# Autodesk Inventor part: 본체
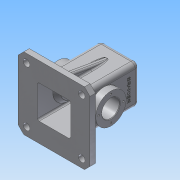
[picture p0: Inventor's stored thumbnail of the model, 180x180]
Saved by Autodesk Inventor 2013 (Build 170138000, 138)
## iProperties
Created: 2016-02
Part Number: 본체
Material: 알루미늄 6061
Document SubType Name: Modeling
Designer: Administrator
Density: 2.71 g/cm^3
Mass: 931.555 g
Surface Area: 1047.27 cm^2
Volume: 343.747 cm^3
Author: Administrator
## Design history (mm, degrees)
sketch "스케치3"
  geometry: L1 (-35, 35)-(35, 35); L2 (35, 35)-(35, -35); L3 (35, -35)-(-35, -35); L4 (-35, -35)-(-35, 35); L5 (-35, 35)-(35, -35); L6 (35, 35)-(-35, -35); 1 further point
  constraints: 12 end point, 2 midpoint, 2 parallel, 1 horizontal, 1 perpendicular
  dimensions: "d4" = 70 distance of L2.end L3.end; "d5" = 70 distance of L1.end L2.end
extrude "돌출2" new body sketch "스케치3" distance "d6" = 120; taper "d7" = 0 deg
feature "쉘2" dims "d8" = 5
sketch "스케치4"
  geometry: L1 (35, 35)-(-35, 35) reference; L2 (-35, 35)-(-35, -35) reference; L3 (-35, -35)-(35, -35) reference; L4 (35, -35)-(35, 35) reference; L5 (65, -65)-(-65, -65); L6 (-65, -65)-(-65, 65); L7 (-65, 65)-(65, 65); L8 (65, 65)-(65, -65); L9 (65, -65)-(-65, 65); L10 (-65, -65)-(65, 65); 1 further point
  constraints: 12 end point, 2 midpoint, 2 parallel, 1 horizontal, 1 perpendicular
  dimensions: "d9" = 130 distance of L6.end L7.end; "d10" = 130 distance of L5.end L6.end
extrude "돌출3" join sketch "스케치4" distance "d11" = 10; taper "d12" = 0 deg
sketch "스케치5"
  geometry: C1 r 20 at (0, 0); 1 further point
  constraints: 1 centre point, 1 coincident
  dimensions: "d13" = 40 diameter of C1
extrude "돌출4" join sketch "스케치5" distance "d14" = 10; taper "d15" = -10 deg
hole "구멍1" diameter "d18" = 21; stored, may be unused: countersink angle "d22" = 90 deg, drill point angle "d24" = 118 deg; dims "d16" = 10, "d17" = 10, "d19" = 6, "d20" = 28, "d21" = 4, "d23" = 8
sketch "스케치6"
  geometry: L1 (70, 0)-(0, 0) reference; L2 (-30, -120)-(100, -120) reference; C1 r 27.5 at (35, -65); 2 further points
  constraints: 1 centre point, 1 midpoint, 1 vertical alignment
  dimensions: "d25" = 55 diameter of C1; "d27" = 55 distance from line of C1.centre L2
extrude "돌출6" join sketch "스케치6" distance "d30" = 13; taper "d31" = 0 deg
sketch "스케치8"
  geometry: L1 (65, 120)-(65, 10) reference; C1 r 27.5 at (30, 55) reference; C2 r 27.5 at (30, 55); 1 further point
  constraints: 1 centre point, 1 coincident
  dimensions: "d32" = 55 diameter of C2
extrude "돌출7" join sketch "스케치8" distance "d33" = 7; taper "d34" = -45 deg
sketch "스케치9"
  geometry: C1 r 27.5 at (0, 0) reference; C2 r 16 at (0, 0); 1 further point
  constraints: 1 centre point, 1 coincident
  dimensions: "d35" = 32 diameter of C2
extrude "돌출8" cut sketch "스케치9" stored distance "d36" = 7; taper "d37" = 0 deg
sketch "스케치10"
  geometry: C1 r 16 at (0, 0) reference; 2 further points
  constraints: 1 vertical alignment
  dimensions: "d38" = 22.5 distance of C1.centre point (0, 22.5)
hole "구멍2" sketch "스케치10" at (0, 22.5) diameter "d39" = 3.242; stored, may be unused: countersink angle "d43" = 90 deg, drill point angle "d45" = 118 deg; dims "d40" = 8, "d41" = 28, "d42" = 4, "d44" = 10
sketch "스케치11"
  geometry: L1 (-110, -50)-(-24.931, -35); L2 (-120, -30)-(-5, -30) reference; L3 (-5, -30)-(-5, -10.5) reference; L4 (-5, -10.5)-(6, -10.5) reference; L5 (6, -10.5)-(6, -14) reference; L6 (6, -14)-(10, -14) reference; L7 (10, -14)-(10, -18.237) reference; L8 (10, -18.237)-(0, -20) reference; L9 (0, -20)-(0, -35) reference; L10 (0, -35)-(-110, -35) reference; L11 (-110, -35)-(-110, -65) reference; L12 (-110, -65)-(-120, -65) reference; L13 (-120, -65)-(-120, -30) reference; L14 (-5, 30)-(-120, 30) reference; L15 (-120, 30)-(-120, 65) reference; L16 (-120, 65)-(-110, 65) reference; L17 (-110, 65)-(-110, 35) reference; L18 (-110, 35)-(0, 35) reference; L19 (0, 35)-(0, 20) reference; L20 (0, 20)-(10, 18.237) reference; L21 (10, 18.237)-(10, 14) reference; L22 (10, 14)-(6, 14) reference; L23 (6, 14)-(6, 10.5) reference; L24 (6, 10.5)-(-5, 10.5) reference; L25 (-5, 10.5)-(-5, 30) reference; 1 further point
  constraints: 2 end point, 1 midpoint, 1 point on line
  dimensions: "d49" = 15 distance from line of L1.start L12; "d52" = 10 deg angle of L1 L12
extrude "돌출9" join sketch "스케치11" stored distance "d53" = 10; taper "d54" = 0 deg
sketch "스케치12"
  geometry: L1 (65, 65)-(-65, 65) reference; L2 (65, -65)-(65, 65) reference; C1 r 6 at (50, 50); 1 further point
  constraints: 1 centre point
  dimensions: "d55" = 12 diameter of C1; "d57" = 15 distance from line of L2 C1.centre; "d58" = 15 distance from line of C1.centre L1
extrude "돌출10" cut sketch "스케치12" stored distance "d59" = 10; taper "d60" = 0 deg
chamfer "모따기1" distance "d64" = 10; stored, may be unused: second distance "d65" = 2, angle "d66" = 45 deg
chamfer "모따기2" distance "d67" = 1; stored, may be unused: second distance "d68" = 2, angle "d69" = 45 deg
fillet "모깎기1" dims "d70" = 8, "d71" = 3, "d72" = 0.5
fillet "모깎기2" dims "d73" = 0.5
fillet "모깎기3" dims "d74" = 3
fillet "모깎기4" dims "d75" = 3
fillet "모깎기5" dims "d76" = 8
sketch "스케치13"
  geometry: L1 (34.55, -45)-(65, -45) reference; L2 (65, -45)-(65, -55) reference; L3 (65, -55)-(-65, -55) reference; L4 (-65, -55)-(-65, -45) reference; L5 (-65, -45)-(-34.55, -45) reference; L6 (27, -42)-(-27, -42) reference; L7 (27, -5.22)-(27, -42) reference; L8 (-27, -5.22)-(-27, -42) reference; L9 (27, 57)-(27, 5.22) reference; L10 (27, 57)-(-27, 57) reference; L11 (-27, 57)-(-27, 5.22) reference; L12 (-18.237, 75)-(18.237, 75) reference; C1 r 16 at (0, 0) reference; A1 r 27.5 centre (0, 0) between (27, 5.22) and (-27, 5.22) reference; A2 r 27.5 centre (0, 0) between (-27, -5.22) and (27, -5.22) reference; A3 r 27.5 centre (0, 0) between (27, -5.22) and (27, 5.22) reference; A4 r 27.5 centre (0, 0) between (27, 5.22) and (-27, 5.22) reference; A5 r 27.5 centre (0, 0) between (-27, 5.22) and (-27, -5.22) reference; 2 further points
  constraints: 1 vertical alignment, 3 other
  dimensions: "d77" = 30 distance from line of L12 point (0, 45)
feature "엠보싱1" sketch "스케치13" dims "d4" = 70, "d5" = 70, "d9" = 130, "d10" = 130, "d78" = 0.5, "d79" = 0
fillet "모깎기6" dims "d80" = 3
fillet "모깎기7" dims "d81" = 3
fillet "모깎기8" dims "d82" = 0.5
node "솔리드2"
mirror "대칭2"
pattern_circular "원형 패턴1" dims angle "d47" = 360 deg
mirror "대칭3"
mirror "대칭4"
pattern_circular "원형 패턴2" dims angle "d62" = 360 deg
node "절단 모서리 투영1"
node "절단 모서리 투영2"
